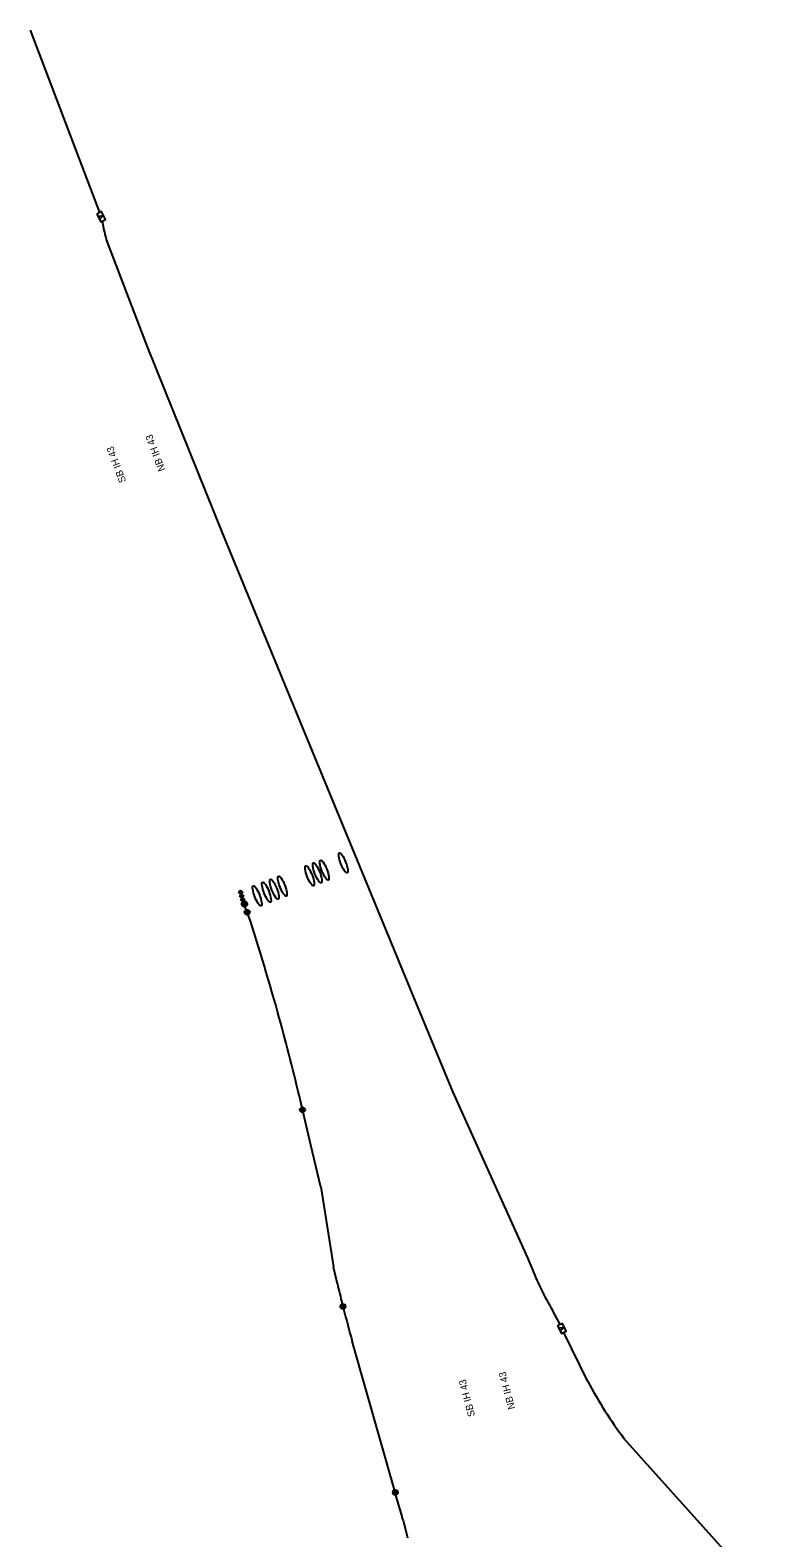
# Model space of a CAD drawing. Extents: x 601562 to 605316, y 332050 to 402250.
# Drawn here: x 603051 to 604143, y 350247 to 352480 of the extents above; entities that cross this region are included whole.
import ezdxf

# ---------------------------------------------------------------- set-up
doc = ezdxf.new("R2010")
doc.units = 0
doc.layers.add('P_FTMS', color=7, linetype='Continuous')
doc.layers.add('P_FTMSConduit', color=7, linetype='Continuous')

# ---------------------------------------------------------------- blocks, each defined once
blk = doc.blocks.new('FMD')
at = {"layer": 'P_FTMS'}
for p, q in [((17, 18), (-17, 18)), ((-16, 16), (-16, 18)), ((16, 16), (-16, 16)), ((-15, 15), (-15, 20)), ((15, 19), (-15, 19)), ((15, 15), (-15, 15)), ((14, 20), (-14, 20)), ((13, 22), (-13, 22)), ((-13, 13), (-13, 21)), ((13, 13), (-13, 13)), ((-12, 12), (-12, 23)), ((12, 12), (-12, 12)), ((11, 23), (-11, 23)), ((10, 25), (-10, 25)), ((-10, 10), (-10, 24)), ((10, 10), (-10, 10)), ((-9, 9), (-9, 26)), ((9, 9), (-9, 9)), ((8, 26), (-8, 26)), ((7, 28), (-7, 28)), ((-7, 7), (-7, 27)), ((7, 7), (-7, 7)), ((-6, 6), (-6, 29)), ((6, 6), (-6, 6)), ((5, 29), (-5, 29)), ((4, 31), (-4, 31)), ((-4, 4), (-4, 30)), ((4, 4), (-4, 4)), ((-3, 3), (-3, 32)), ((3, 3), (-3, 3)), ((2, 32), (-2, 32)), ((1, 34), (-1, 34)), ((-1, 1), (-1, 33)), ((1, 1), (-1, 1)), ((0, 0), (0, 34)), ((1, 1), (1, 33)), ((3, 3), (3, 32)), ((4, 4), (4, 30)), ((6, 6), (6, 29)), ((7, 7), (7, 27)), ((9, 9), (9, 26)), ((10, 10), (10, 24)), ((12, 12), (12, 23)), ((13, 13), (13, 21)), ((15, 15), (15, 20)), ((16, 16), (16, 18))]:
    blk.add_line(p, q, dxfattribs=at)
blk.add_lwpolyline([(-17, 17), (0, 34), (17, 17), (0, 0)], close=True, dxfattribs=at)
blk = doc.blocks.new('_U230')
at = {"layer": 'P_FTMS'}
for p, q in [((12.1, 1.6), (-12.2, -0.1)), ((11.8, 3), (-12.1, 1.4)), ((11.9, 2.3), (-12.1, 0.6)), ((12.1, 0.8), (-12.1, -0.8)), ((12.1, 0.1), (-12.1, -1.6)), ((11.6, 3.7), (-12, 2.1)), ((-11.9, 2.5), (-11.4, -4.2)), ((11.3, 4.4), (-11.8, 2.9)), ((11, 5.2), (-11.6, 3.6)), ((10.6, 5.9), (-11.4, 4.4)), ((-11.3, 4.5), (-10.6, -6)), ((10.2, 6.6), (-11, 5.1)), ((9.8, 7.3), (-10.7, 5.9)), ((-10.7, 5.9), (-9.8, -7.2)), ((9.2, 8), (-10.2, 6.6)), ((-10, 6.9), (-9, -8.2)), ((8.6, 8.6), (-9.7, 7.4)), ((-9.3, 7.8), (-8.2, -9)), ((7.8, 9.3), (-9, 8.2)), ((-8.6, 8.5), (-7.4, -9.6)), ((6.9, 10), (-8.2, 9)), ((-8, 9.2), (-6.6, -10.2)), ((-7.3, 9.7), (-5.9, -10.6)), ((5.8, 10.7), (-7.2, 9.8)), ((-6.6, 10.3), (-5.1, -11)), ((4.5, 11.3), (-6, 10.6)), ((-5.9, 10.7), (-4.4, -11.4)), ((-5.1, 11), (-3.6, -11.6)), ((-4.4, 11.3), (-2.9, -11.8)), ((2.5, 11.9), (-4.1, 11.5)), ((-3.7, 11.6), (-2.1, -12)), ((-3, 11.8), (-1.4, -12.1)), ((-2.3, 12), (-0.6, -12.2)), ((-1.6, 12.1), (0.1, -12.2)), ((-0.8, 12.1), (0.8, -12.1)), ((-0.1, 12.2), (1.6, -12.1)), ((0.6, 12.1), (2.3, -11.9)), ((1.4, 12.1), (3, -11.8)), ((2.1, 12), (3.7, -11.6)), ((2.9, 11.8), (4.4, -11.3)), ((3.6, 11.6), (5.1, -11)), ((4.4, 11.3), (5.9, -10.7)), ((5.1, 11), (6.6, -10.2)), ((5.9, 10.6), (7.3, -9.8)), ((6.6, 10.2), (8, -9.2)), ((7.4, 9.7), (8.6, -8.6)), ((8.2, 9), (9.3, -7.8)), ((9, 8.2), (10, -6.9)), ((9.8, 7.2), (10.7, -5.8)), ((10.6, 5.9), (11.3, -4.5)), ((11.5, 4), (11.9, -2.5)), ((12.1, -0.6), (-12, -2.3)), ((12.1, -1.4), (-11.8, -3)), ((12, -2.1), (-11.6, -3.7)), ((11.8, -2.9), (-11.3, -4.4)), ((11.6, -3.6), (-11, -5.1)), ((11.3, -4.4), (-10.7, -5.9)), ((11.1, -5.1), (-10.2, -6.6)), ((10.6, -5.9), (-9.8, -7.3)), ((10.2, -6.6), (-9.2, -8)), ((9.6, -7.4), (-8.5, -8.6)), ((9, -8.2), (-7.8, -9.3)), ((8.2, -9), (-6.9, -10)), ((7.3, -9.8), (-5.8, -10.7)), ((6, -10.6), (-4.5, -11.3)), ((4.1, -11.5), (-2.6, -11.9))]:
    blk.add_line(p, q, dxfattribs=at)
blk.add_circle((0, 0), 12.2, dxfattribs=at)
blk = doc.blocks.new('FTMS_FCV')
at = {"layer": 'P_FTMS'}
blk.add_line((13, 16), (1, -22), dxfattribs=at)
blk.add_lwpolyline([(39, 24), (-39, 24), (-39, -24), (39, -24)], close=True, dxfattribs=at)
blk.add_lwpolyline([(-12, 16), (1, -22)], dxfattribs=at)

msp = doc.modelspace()

# ---------------------------------------------------------------- linework, layer by layer
at = {"layer": 'P_FTMS'}
for centre in [(603372, 351173.7), (603453.9, 350881), (603513.8, 350589.8), (603591.6, 350314.2)]:
    msp.add_circle(centre, 3.75, dxfattribs=at)
for centre, start, end in [((603371.6, 351178.2), 222.4831, 328.7387), ((603372.5, 351169.3), 42.4831, 148.7387), ((603453.4, 350885.5), 222.4831, 328.7387), ((603454.3, 350876.5), 42.4831, 148.7387), ((603513.4, 350594.2), 222.4831, 328.7387), ((603514.2, 350585.3), 42.4831, 148.7387), ((603591.2, 350318.7), 222.4831, 328.7387), ((603592.1, 350309.7), 42.4831, 148.7387)]:
    msp.add_arc(centre, 3.75, start, end, dxfattribs=at)
for centre in [(603514.3, 351246.7), (603464.5, 351227.7), (603475.8, 351232), (603486.3, 351236.1), (603386.8, 351198), (603400.6, 351203.3), (603412.2, 351207.7), (603424.2, 351212.4)]:
    msp.add_ellipse(centre, major_axis=(-5.8, 14.9), ratio=0.23471, dxfattribs=at)
at = {"layer": 'P_FTMSConduit'}
for p, q in [((603050.6, 352480.4), (603153.5, 352210)), ((603157.4, 352197.6), (603160.4, 352181.9)), ((603165.2, 352164.9), (603223.8, 352011.2)), ((603223.7, 352011.3), (603336, 351733.1)), ((603335.9, 351733.2), (603619.4, 351045.5)), ((603368, 351181.8), (603370.8, 351177.3)), ((603619.4, 351045.5), (603676.1, 350908)), ((603676.1, 350908.1), (603787.3, 350661.9)), ((603453, 350885.4), (603450.8, 350894.8)), ((603466.4, 350828.6), (603454.8, 350877.7)), ((603481, 350766.6), (603466.4, 350828.6)), ((603480.9, 350766.9), (603499.6, 350648.5)), ((603787.4, 350661.9), (603792.3, 350649.8)), ((603505.6, 350623.1), (603499.7, 350648)), ((603835.4, 350562.8), (603824.2, 350584.1)), ((603590.2, 350317.9), (603527.6, 350538.4)), ((603601.3, 350278.6), (603592.3, 350310.3)), ((603602.8, 350272.9), (603609.4, 350246.9))]:
    msp.add_line(p, q, dxfattribs=at)
for points in [[(603876.5, 350478.4), (603841, 350551.3)], [(604143.2, 350156.7), (603930.1, 350394.2)]]:
    msp.add_lwpolyline(points, dxfattribs=at)
for centre, radius, start, end in [((603258.7, 352200.5), 100, 190.7361, 200.8548), ((600155.9, 350118.9), 3385, 15.3877, 18.0896), ((600155.9, 350118.9), 3385, 13.2512, 15.3877), ((604146.9, 350781.2), 378.1, 200.3265, 211.4184), ((605378.3, 351064.1), 1923.9, 193.2512, 194.1471), ((605378.3, 351064.1), 1923.9, 194.3852, 195.857), ((604448.2, 350783.1), 647.8, 208.0583, 216.8871), ((599644.8, 349265.5), 4084.2, 14.2797, 14.365)]:
    msp.add_arc(centre, radius, start, end, dxfattribs=at)

# ---------------------------------------------------------------- block references
at = {"layer": 'P_FTMS'}
for name, p, xscale, yscale, rotation in [('FTMS_FCV', (603155.7, 352204), 0.16404166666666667, 0.16404166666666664, 116.16065668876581), ('FMD', (603359.6, 351202.6), 0.16404166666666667, 0.16404166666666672, -74.13394312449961), ('FMD', (603361.3, 351196.8), 0.16404166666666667, 0.16404166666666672, -74.13394312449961), ('FMD', (603362.8, 351191.4), 0.16404166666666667, 0.16404166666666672, -74.13394312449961), ('_U230', (603367.9, 351185.8), 0.32808333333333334, 0.32808333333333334, 19.97319264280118), ('FTMS_FCV', (603838.2, 350557.1), 0.16404166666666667, 0.16404166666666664, 116.16065668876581)]:
    msp.add_blockref(name, p, dxfattribs=dict(at, xscale=xscale, yscale=yscale, rotation=rotation))

# ---------------------------------------------------------------- texts
at = {"layer": 'P_FTMSConduit'}
for s, rotation, p in [('NB IH 43', 110.5095, (603250.8, 351829.1)), ('SB IH 43', 110.5095, (603192.9, 351812.3)), ('SB IH 43', 104.6085, (603709.6, 350428)), ('NB IH 43', 104.6085, (603769, 350438.7))]:
    msp.add_text(s, height=10.5, rotation=rotation, dxfattribs=at).set_placement(p)

doc.saveas('drawing.dxf')
